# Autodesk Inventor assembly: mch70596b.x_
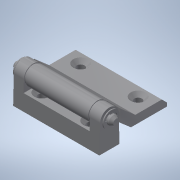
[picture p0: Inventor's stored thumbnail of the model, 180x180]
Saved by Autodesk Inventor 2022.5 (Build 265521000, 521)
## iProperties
Part Number: mch70596b.x_
Material: 一般
Document SubType Name: Assembly
Designer: ImaoCorp
Sending System: SOLIDWORKS 2017-2017317
MC: AMD64
MC_MODEL: Intel64 Family 6 Model 60 Stepping 3, GenuineIntel
OS: Windows_NT
FRU: Parasolid Version 29.0, build 201,  4-17-2017
FORMAT: text
GUISE: transmit
KEY: mch70596b
FILE: mch70596b.x_t
DATE: Fri Jul 26 11:41:59 2019
Author: ImaoCorp
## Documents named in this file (4)
- X:\14_SW2022-Inv2022\00_全2023-1023新製品(TCC)まで\m\mch70596b\MCH70596B.iam
- X:\14_SW2022-Inv2022\00_全2023-1023新製品(TCC)まで\m\mch70596b\mch70596b_01.ipt
- X:\14_SW2022-Inv2022\00_全2023-1023新製品(TCC)まで\m\mch70596b\mch70596b_02.ipt
- X:\14_SW2022-Inv2022\00_全2023-1023新製品(TCC)まで\m\mch70596b\mch70596b_03.ipt
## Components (3 placed, 3 different names)
1. mch70596b_01
2. mch70596b_02
3. mch70596b_03
